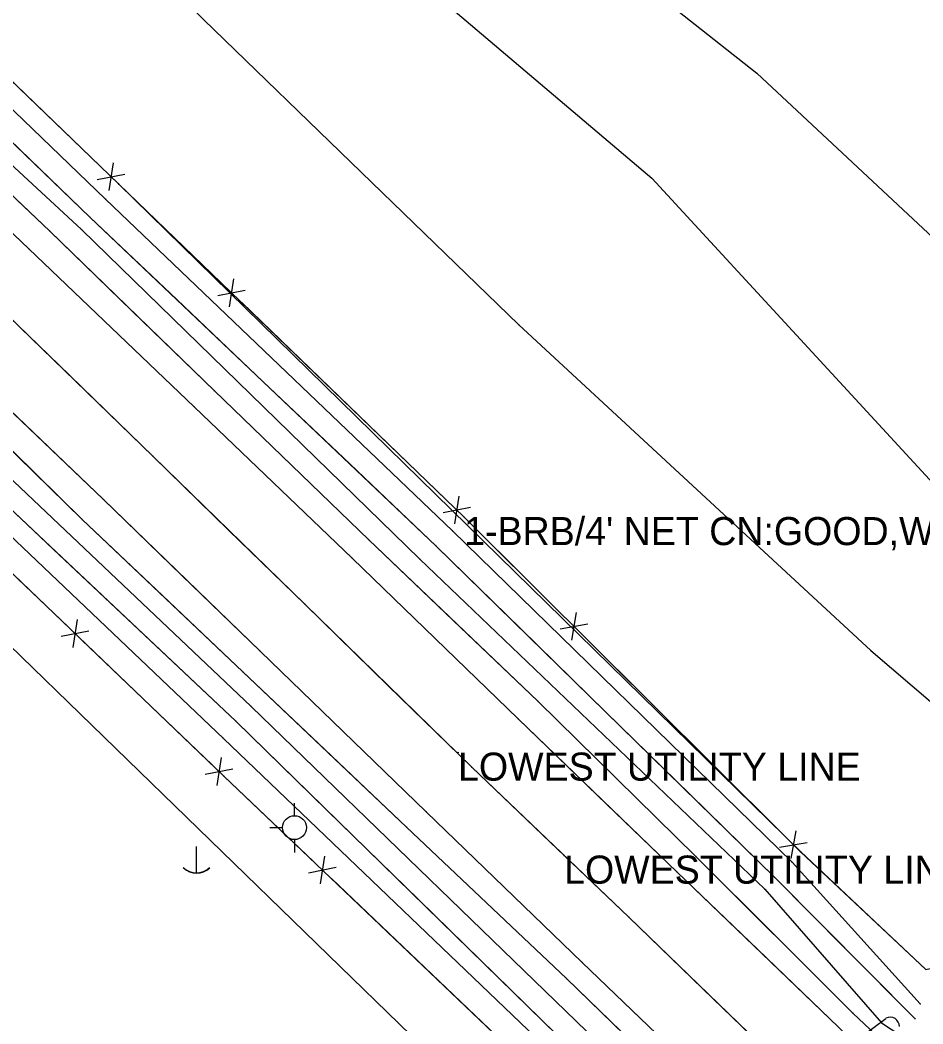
# Model space of a CAD drawing. Extents: x -99999 to 591807, y -99999 to 347168.
# Drawn here: x 588067.4 to 588228.1, y 346318.1 to 346496.8 of the extents above; entities that cross this region are included whole.
import ezdxf

# ---------------------------------------------------------------- set-up
doc = ezdxf.new("R2010")
doc.units = 0
for name, color, linetype in [('S_BREAKLINE', 7, 'Continuous'), ('S_DITCHLINE', 7, 'Continuous'), ('S_EDGE_PAVEMENT', 7, 'Continuous'), ('S_ELECTRIC_UTILITIES_ANNOT', 7, 'Continuous'), ('S_FENCE', 7, 'Continuous'), ('S_FENCE_ANNOT', 7, 'Continuous'), ('S_GRD_PT_SYM', 7, 'Continuous'), ('S_MAILBOX', 7, 'Continuous'), ('S_MSC_PT_SYM', 7, 'Continuous'), ('S_PAVEMENT_CROWN', 7, 'Continuous'), ('S_RDW_PT_SYM', 7, 'Continuous'), ('S_SHOULDER', 7, 'Continuous'), ('S_UTILITY_POLE', 7, 'Continuous'), ('S_UTL_PT_SYM', 7, 'Continuous'), ('S_WATER_UTILITIES', 7, 'Continuous')]:
    doc.layers.add(name, color=color, linetype=linetype)

msp = doc.modelspace()

# ---------------------------------------------------------------- linework, layer by layer
at = {"layer": 'S_BREAKLINE'}
for points in [[(588079.01, 346587.76), (588136.65, 346536.23), (588198.57, 346487.33), (588257.7, 346432.13), (588290.98, 346405.27)], [(588068.82, 346576.78), (588120.74, 346518.8), (588179.85, 346468.66), (588236.95, 346406.71), (588277.38, 346385.2)], [(588044.07, 346552.25), (588100.02, 346496.92), (588156.19, 346442.58), (588218.84, 346384.62), (588256.48, 346352.46)], [(588019.86, 346530.29), (588084.91, 346467.67), (588206.31, 346348.84), (588228.63, 346327.82), (588249.2, 346332.53)], [(588017.81, 346527.33), (588082.58, 346464.95), (588144.38, 346405.87), (588204.84, 346346.9), (588227.65, 346321.7)], [(588012.4, 346520.54), (588078.31, 346459.52), (588138.59, 346400.83), (588199.97, 346342.1), (588220.75, 346318.33), (588226.1, 346314.84), (588229.3, 346314.78), (588230.76, 346317.53)], [(587985.01, 346494.14), (588043.41, 346436.28), (588108.56, 346374.61), (588173.85, 346311.36), (588242.38, 346247.25), (588302.7, 346186.99), (588369.16, 346122.22), (588383.21, 346097.17), (588432.31, 346045.45), (588485.71, 345983.72), (588533.05, 345919.6)], [(587978.95, 346487.85), (588038.25, 346431.02), (588103.62, 346368.92), (588168.93, 346306.43), (588238, 346241.18), (588296.13, 346179.85), (588360.54, 346112.54), (588377.94, 346092.95), (588425.83, 346037.79), (588477.63, 345977.56), (588525.63, 345916.46)]]:
    msp.add_lwpolyline(points, dxfattribs=at)
at = {"layer": 'S_DITCHLINE'}
for points in [[(588015.07, 346524.14), (588079.87, 346461.68), (588141.49, 346403.19), (588201.74, 346344.19), (588226.74, 346319.06)], [(588015.07, 346524.14), (588031.27, 346508.52), (588047.47, 346492.91), (588063.67, 346477.29), (588079.87, 346461.68), (588095.28, 346447.05), (588110.68, 346432.43), (588126.09, 346417.81), (588141.49, 346403.19), (588156.55, 346388.44), (588171.62, 346373.69), (588186.68, 346358.94), (588201.74, 346344.19), (588214.24, 346331.62), (588226.74, 346319.06)], [(587981.38, 346490.49), (588040.72, 346433.29), (588105.81, 346371.99), (588170.92, 346308.42), (588239.53, 346243.97), (588298.87, 346183.24), (588365.05, 346118.27), (588381.6, 346095.52), (588429.37, 346040.98), (588482.84, 345982.86), (588529.72, 345920.18), (588553, 345879.12), (588569.51, 345828.65), (588585.87, 345761.88), (588598.5, 345693.11), (588612.58, 345591.71), (588620.74, 345530.5), (588634.95, 345464.48), (588639.41, 345427.12), (588638.6, 345425.11)], [(587981.38, 346490.49), (587996.22, 346476.19), (588011.05, 346461.89), (588025.89, 346447.59), (588040.72, 346433.29), (588056.99, 346417.97), (588073.27, 346402.64), (588089.54, 346387.32), (588105.81, 346371.99), (588122.09, 346356.1), (588138.36, 346340.21), (588154.64, 346324.31), (588170.92, 346308.42)]]:
    msp.add_lwpolyline(points, dxfattribs=at)
at = {"layer": 'S_EDGE_PAVEMENT'}
for points in [[(588006.51, 346515.67), (588037.25, 346486.28), (588068.97, 346456.07), (588098.41, 346427.99), (588126.49, 346401.05), (588156.06, 346372.42), (588184.38, 346345.17), (588213.09, 346317.55), (588241.74, 346289.83), (588275.21, 346257.52), (588304.28, 346229.62), (588334.12, 346200.8), (588363.95, 346171.7), (588391.18, 346144.84), (588419.55, 346117.13), (588447.95, 346088.7), (588472.86, 346062.77), (588495.2, 346037.93), (588515.96, 346012.84), (588538.3, 345983.93), (588553.85, 345961.48), (588569.44, 345935.94), (588581.55, 345913.63)], [(588006.51, 346515.67), (588021.88, 346500.97), (588037.25, 346486.28), (588053.11, 346471.18), (588068.97, 346456.07), (588083.69, 346442.03), (588098.41, 346427.99), (588112.45, 346414.52), (588126.49, 346401.05), (588141.27, 346386.73), (588156.06, 346372.42), (588170.22, 346358.8), (588184.38, 346345.17), (588198.74, 346331.36), (588213.09, 346317.55)], [(587990.04, 346499.66), (588021.44, 346469.83), (588052.98, 346439.41), (588082.26, 346411.47), (588110.16, 346384.47), (588139.71, 346355.89), (588167.47, 346329.09), (588196.94, 346300.74), (588228.68, 346270.07), (588258.37, 346241.41), (588287.79, 346213.57), (588317.3, 346184.82), (588347.78, 346154.95), (588374.65, 346128.54), (588403.23, 346100.42), (588430.53, 346073), (588454.75, 346047.65), (588476.4, 346023.75), (588497.81, 345997.87), (588518.5, 345970.8), (588533.24, 345949.77), (588549.25, 345924.48)], [(587990.04, 346499.66), (588005.74, 346484.74), (588021.44, 346469.83), (588037.21, 346454.62), (588052.98, 346439.41), (588067.62, 346425.44), (588082.26, 346411.47), (588096.21, 346397.97), (588110.16, 346384.47), (588124.94, 346370.18), (588139.71, 346355.89), (588153.59, 346342.49), (588167.47, 346329.09), (588182.21, 346314.92)]]:
    msp.add_lwpolyline(points, dxfattribs=at)
at = {"layer": 'S_FENCE'}
for p, q in [((588019.92, 346530.21), (588084.97, 346467.59)), ((588083.97, 346471.39), (588083.2, 346466.45)), ((588081.13, 346468.44), (588086.04, 346469.4)), ((588084.97, 346467.59), (588146.45, 346408.35)), ((588105.41, 346450.73), (588104.64, 346445.79)), ((588102.57, 346447.78), (588107.48, 346448.74)), ((588025.04, 346437.54), (588103.64, 346362.26)), ((588145.53, 346412.08), (588144.75, 346407.14)), ((588142.69, 346409.13), (588147.6, 346410.09)), ((588146.45, 346408.35), (588206.33, 346348.75)), ((588166.42, 346391.37), (588165.56, 346386.44)), ((588077.54, 346390.1), (588076.78, 346385.15)), ((588074.71, 346387.14), (588079.61, 346388.11)), ((588163.53, 346388.46), (588168.45, 346389.34)), ((588103.18, 346365.54), (588102.42, 346360.59)), ((588100.35, 346362.58), (588105.26, 346363.55)), ((588103.64, 346362.26), (588157.5, 346310.95)), ((588205.49, 346352.48), (588204.63, 346347.55)), ((588202.6, 346349.57), (588207.52, 346350.45)), ((588206.33, 346348.75), (588228.63, 346327.82)), ((588121.58, 346347.99), (588120.84, 346343.05)), ((588118.76, 346345.03), (588123.66, 346346.02))]:
    msp.add_line(p, q, dxfattribs=at)
for points in [[(588043.07, 346507.92), (588081.65, 346470.78)], [(588084.97, 346467.59), (588103.2, 346450.02)], [(588106.85, 346446.51), (588143.32, 346411.37)], [(588146.45, 346408.35), (588164.21, 346390.67)], [(588064.34, 346399.9), (588076, 346388.74)], [(588078.33, 346386.51), (588101.64, 346364.18)], [(588167.76, 346387.14), (588203.29, 346351.78)], [(588103.64, 346362.26), (588119.61, 346347.04)], [(588206.33, 346348.75), (588228.63, 346327.82)], [(588122.81, 346344), (588154.75, 346313.56)]]:
    msp.add_lwpolyline(points, dxfattribs=at)
at = {"layer": 'S_GRD_PT_SYM'}
for points in [[(588198.57, 346487.33), (588198.6, 346487.37), (588198.57, 346487.33), (588198.53, 346487.37), (588198.57, 346487.33), (588198.53, 346487.3), (588198.57, 346487.33), (588198.6, 346487.3)], [(588179.85, 346468.66), (588179.89, 346468.69), (588179.85, 346468.66), (588179.81, 346468.69), (588179.85, 346468.66), (588179.81, 346468.62), (588179.85, 346468.66), (588179.88, 346468.62)], [(588084.91, 346467.67), (588084.95, 346467.71), (588084.91, 346467.67), (588084.88, 346467.71), (588084.91, 346467.67), (588084.88, 346467.64), (588084.91, 346467.67), (588084.95, 346467.64)], [(588082.58, 346464.95), (588082.62, 346464.99), (588082.58, 346464.95), (588082.54, 346464.99), (588082.58, 346464.95), (588082.55, 346464.91), (588082.58, 346464.95), (588082.62, 346464.92)], [(588079.87, 346461.68), (588079.91, 346461.71), (588079.87, 346461.68), (588079.83, 346461.71), (588079.87, 346461.68), (588079.84, 346461.64), (588079.87, 346461.68), (588079.91, 346461.64)], [(588078.31, 346459.52), (588078.34, 346459.56), (588078.31, 346459.52), (588078.27, 346459.56), (588078.31, 346459.52), (588078.27, 346459.49), (588078.31, 346459.52), (588078.34, 346459.49)], [(588156.19, 346442.58), (588156.22, 346442.61), (588156.19, 346442.58), (588156.15, 346442.61), (588156.19, 346442.58), (588156.15, 346442.54), (588156.19, 346442.58), (588156.22, 346442.54)], [(588144.38, 346405.87), (588144.41, 346405.91), (588144.38, 346405.87), (588144.34, 346405.91), (588144.38, 346405.87), (588144.34, 346405.84), (588144.38, 346405.87), (588144.41, 346405.84)], [(588141.49, 346403.19), (588141.53, 346403.22), (588141.49, 346403.19), (588141.46, 346403.22), (588141.49, 346403.19), (588141.46, 346403.15), (588141.49, 346403.19), (588141.53, 346403.15)], [(588138.59, 346400.83), (588138.62, 346400.86), (588138.59, 346400.83), (588138.55, 346400.86), (588138.59, 346400.83), (588138.55, 346400.79), (588138.59, 346400.83), (588138.63, 346400.79)], [(588218.84, 346384.62), (588218.88, 346384.65), (588218.84, 346384.62), (588218.81, 346384.65), (588218.84, 346384.62), (588218.81, 346384.58), (588218.84, 346384.62), (588218.88, 346384.58)], [(588108.56, 346374.61), (588108.59, 346374.64), (588108.56, 346374.61), (588108.52, 346374.64), (588108.56, 346374.61), (588108.52, 346374.57), (588108.56, 346374.61), (588108.59, 346374.57)], [(588105.81, 346371.99), (588105.84, 346372.03), (588105.81, 346371.99), (588105.77, 346372.03), (588105.81, 346371.99), (588105.77, 346371.96), (588105.81, 346371.99), (588105.85, 346371.96)], [(588103.62, 346368.92), (588103.65, 346368.96), (588103.62, 346368.92), (588103.58, 346368.96), (588103.62, 346368.92), (588103.58, 346368.89), (588103.62, 346368.92), (588103.65, 346368.89)], [(588145.36, 346366.43), (588145.36, 346366.48), (588145.36, 346366.43), (588145.31, 346366.43), (588145.36, 346366.43), (588145.36, 346366.38), (588145.36, 346366.43), (588145.41, 346366.43)], [(588206.31, 346348.84), (588206.35, 346348.88), (588206.31, 346348.84), (588206.28, 346348.88), (588206.31, 346348.84), (588206.28, 346348.81), (588206.31, 346348.84), (588206.35, 346348.81)], [(588164.25, 346348.1), (588164.25, 346348.15), (588164.25, 346348.1), (588164.2, 346348.1), (588164.25, 346348.1), (588164.25, 346348.05), (588164.25, 346348.1), (588164.3, 346348.1)], [(588204.84, 346346.9), (588204.88, 346346.94), (588204.84, 346346.9), (588204.81, 346346.94), (588204.84, 346346.9), (588204.8, 346346.87), (588204.84, 346346.9), (588204.87, 346346.87)], [(588201.74, 346344.19), (588201.77, 346344.22), (588201.74, 346344.19), (588201.7, 346344.22), (588201.74, 346344.19), (588201.7, 346344.15), (588201.74, 346344.19), (588201.77, 346344.15)], [(588199.97, 346342.1), (588200.01, 346342.13), (588199.97, 346342.1), (588199.94, 346342.13), (588199.97, 346342.1), (588199.93, 346342.06), (588199.97, 346342.1), (588200, 346342.06)], [(588227.65, 346321.7), (588227.69, 346321.74), (588227.65, 346321.7), (588227.62, 346321.74), (588227.65, 346321.7), (588227.62, 346321.67), (588227.65, 346321.7), (588227.69, 346321.66)], [(588220.75, 346318.33), (588220.78, 346318.37), (588220.75, 346318.33), (588220.71, 346318.36), (588220.75, 346318.33), (588220.72, 346318.29), (588220.75, 346318.33), (588220.79, 346318.3)], [(588226.74, 346319.06), (588226.77, 346319.1), (588226.74, 346319.06), (588226.7, 346319.1), (588226.74, 346319.06), (588226.7, 346319.03), (588226.74, 346319.06), (588226.77, 346319.03)]]:
    msp.add_lwpolyline(points, close=True, dxfattribs=at)
at = {"layer": 'S_MAILBOX'}
msp.add_line((588217.4, 346316.02), (588221.53, 346319.13), dxfattribs=at)
msp.add_arc((588222.3, 346317.66), 1.66, 0, 117.5718, dxfattribs=at)
at = {"layer": 'S_MSC_PT_SYM'}
for points in [[(588084.97, 346467.59), (588084.97, 346467.64), (588084.97, 346467.59), (588084.92, 346467.59), (588084.97, 346467.59), (588084.97, 346467.54), (588084.97, 346467.59), (588085.02, 346467.59)], [(588146.45, 346408.35), (588146.45, 346408.4), (588146.45, 346408.35), (588146.4, 346408.35), (588146.45, 346408.35), (588146.45, 346408.3), (588146.45, 346408.35), (588146.5, 346408.35)], [(588146.45, 346408.35), (588146.45, 346408.4), (588146.45, 346408.35), (588146.4, 346408.35), (588146.45, 346408.35), (588146.45, 346408.3), (588146.45, 346408.35), (588146.5, 346408.35)], [(588103.64, 346362.26), (588103.64, 346362.31), (588103.64, 346362.26), (588103.59, 346362.26), (588103.64, 346362.26), (588103.64, 346362.21), (588103.64, 346362.26), (588103.69, 346362.26)], [(588206.33, 346348.75), (588206.33, 346348.8), (588206.33, 346348.75), (588206.28, 346348.75), (588206.33, 346348.75), (588206.33, 346348.7), (588206.33, 346348.75), (588206.38, 346348.75)]]:
    msp.add_lwpolyline(points, dxfattribs=at)
at = {"layer": 'S_PAVEMENT_CROWN'}
for points in [[(587997.94, 346508.04), (588029.71, 346477.77), (588061.36, 346447.92), (588091.09, 346419.11), (588118.07, 346392.84), (588147.79, 346363.81), (588175.77, 346337.12), (588205.85, 346308.09), (588236.22, 346278.66), (588266.55, 346249.5), (588296.48, 346221.11), (588325.95, 346192.27), (588355.72, 346163.52), (588383.28, 346136.41), (588411.18, 346108.72), (588439.24, 346080.6), (588464.53, 346055.01), (588485.92, 346030.52), (588506.56, 346005.75), (588528.34, 345977.31), (588543.88, 345955.52), (588560.06, 345929.96), (588571.31, 345908.67)], [(587997.94, 346508.04), (588013.83, 346492.91), (588029.71, 346477.77), (588045.53, 346462.85), (588061.36, 346447.92), (588076.23, 346433.52), (588091.09, 346419.11), (588104.58, 346405.98), (588118.07, 346392.84), (588132.93, 346378.33), (588147.79, 346363.81), (588161.78, 346350.46), (588175.77, 346337.12), (588190.81, 346322.6), (588205.85, 346308.09)]]:
    msp.add_lwpolyline(points, dxfattribs=at)
at = {"layer": 'S_RDW_PT_SYM'}
for points in [[(588072.71, 346459.21), (588072.75, 346459.25), (588072.71, 346459.21), (588072.67, 346459.24), (588072.71, 346459.21), (588072.68, 346459.17), (588072.71, 346459.21), (588072.75, 346459.18)], [(588068.97, 346456.07), (588069, 346456.11), (588068.97, 346456.07), (588068.93, 346456.11), (588068.97, 346456.07), (588068.93, 346456.04), (588068.97, 346456.07), (588069, 346456.04)], [(588102.02, 346430.81), (588102.05, 346430.84), (588102.02, 346430.81), (588101.98, 346430.84), (588102.02, 346430.81), (588101.98, 346430.77), (588102.02, 346430.81), (588102.06, 346430.77)], [(588098.41, 346427.99), (588098.45, 346428.03), (588098.41, 346427.99), (588098.38, 346428.02), (588098.41, 346427.99), (588098.38, 346427.95), (588098.41, 346427.99), (588098.45, 346427.96)], [(588091.09, 346419.11), (588091.13, 346419.15), (588091.09, 346419.11), (588091.06, 346419.15), (588091.09, 346419.11), (588091.06, 346419.08), (588091.09, 346419.11), (588091.13, 346419.08)], [(588082.26, 346411.47), (588082.29, 346411.51), (588082.26, 346411.47), (588082.22, 346411.51), (588082.26, 346411.47), (588082.23, 346411.44), (588082.26, 346411.47), (588082.3, 346411.44)], [(588078.44, 346407.93), (588078.48, 346407.96), (588078.44, 346407.93), (588078.41, 346407.96), (588078.44, 346407.93), (588078.41, 346407.89), (588078.44, 346407.93), (588078.48, 346407.89)], [(588129.46, 346404.3), (588129.49, 346404.34), (588129.46, 346404.3), (588129.42, 346404.34), (588129.46, 346404.3), (588129.42, 346404.27), (588129.46, 346404.3), (588129.5, 346404.27)], [(588126.49, 346401.05), (588126.52, 346401.08), (588126.49, 346401.05), (588126.45, 346401.08), (588126.49, 346401.05), (588126.45, 346401.01), (588126.49, 346401.05), (588126.52, 346401.01)], [(588118.07, 346392.84), (588118.11, 346392.88), (588118.07, 346392.84), (588118.04, 346392.88), (588118.07, 346392.84), (588118.04, 346392.81), (588118.07, 346392.84), (588118.11, 346392.81)], [(588110.16, 346384.47), (588110.19, 346384.51), (588110.16, 346384.47), (588110.12, 346384.51), (588110.16, 346384.47), (588110.12, 346384.44), (588110.16, 346384.47), (588110.19, 346384.44)], [(588107.07, 346380.79), (588107.11, 346380.83), (588107.07, 346380.79), (588107.04, 346380.83), (588107.07, 346380.79), (588107.04, 346380.76), (588107.07, 346380.79), (588107.11, 346380.76)], [(588159.58, 346375.55), (588159.61, 346375.59), (588159.58, 346375.55), (588159.54, 346375.59), (588159.58, 346375.55), (588159.54, 346375.52), (588159.58, 346375.55), (588159.61, 346375.52)], [(588156.06, 346372.42), (588156.1, 346372.46), (588156.06, 346372.42), (588156.03, 346372.45), (588156.06, 346372.42), (588156.03, 346372.38), (588156.06, 346372.42), (588156.1, 346372.38)], [(588147.79, 346363.81), (588147.83, 346363.85), (588147.79, 346363.81), (588147.76, 346363.85), (588147.79, 346363.81), (588147.76, 346363.78), (588147.79, 346363.81), (588147.83, 346363.78)], [(588139.71, 346355.89), (588139.75, 346355.93), (588139.71, 346355.89), (588139.68, 346355.93), (588139.71, 346355.89), (588139.68, 346355.86), (588139.71, 346355.89), (588139.75, 346355.86)], [(588136.2, 346353.17), (588136.24, 346353.21), (588136.2, 346353.17), (588136.17, 346353.21), (588136.2, 346353.17), (588136.17, 346353.14), (588136.2, 346353.17), (588136.24, 346353.14)], [(588187.72, 346347.96), (588187.75, 346348), (588187.72, 346347.96), (588187.68, 346348), (588187.72, 346347.96), (588187.68, 346347.93), (588187.72, 346347.96), (588187.75, 346347.93)], [(588184.38, 346345.17), (588184.41, 346345.21), (588184.38, 346345.17), (588184.34, 346345.21), (588184.38, 346345.17), (588184.34, 346345.14), (588184.38, 346345.17), (588184.42, 346345.14)], [(588175.77, 346337.12), (588175.81, 346337.15), (588175.77, 346337.12), (588175.74, 346337.15), (588175.77, 346337.12), (588175.74, 346337.08), (588175.77, 346337.12), (588175.81, 346337.08)], [(588167.47, 346329.09), (588167.51, 346329.13), (588167.47, 346329.09), (588167.44, 346329.13), (588167.47, 346329.09), (588167.44, 346329.06), (588167.47, 346329.09), (588167.51, 346329.06)], [(588164.68, 346326.19), (588164.71, 346326.23), (588164.68, 346326.19), (588164.64, 346326.23), (588164.68, 346326.19), (588164.64, 346326.16), (588164.68, 346326.19), (588164.71, 346326.16)], [(588215.66, 346320.05), (588215.7, 346320.09), (588215.66, 346320.05), (588215.63, 346320.08), (588215.66, 346320.05), (588215.63, 346320.01), (588215.66, 346320.05), (588215.7, 346320.02)]]:
    msp.add_lwpolyline(points, close=True, dxfattribs=at)
at = {"layer": 'S_SHOULDER'}
for points in [[(588010.2, 346518.27), (588040.87, 346489.37), (588072.71, 346459.21), (588102.02, 346430.81), (588129.46, 346404.3), (588159.58, 346375.55), (588187.72, 346347.96), (588215.66, 346320.05), (588223.88, 346312.27)], [(588010.2, 346518.27), (588025.53, 346503.82), (588040.87, 346489.37), (588056.79, 346474.29), (588072.71, 346459.21), (588087.36, 346445.01), (588102.02, 346430.81), (588115.74, 346417.56), (588129.46, 346404.3), (588144.52, 346389.93), (588159.58, 346375.55), (588173.65, 346361.76), (588187.72, 346347.96), (588201.69, 346334.01), (588215.66, 346320.05), (588223.88, 346312.27)], [(587987.1, 346496.67), (588018.38, 346466.6), (588049.78, 346436.07), (588078.44, 346407.93), (588107.07, 346380.79), (588136.2, 346353.17), (588164.68, 346326.19), (588193.77, 346298.03), (588226.04, 346266.74), (588255.76, 346238.66), (588285.11, 346210.85), (588314.36, 346182.4), (588345, 346152.62), (588372.24, 346126.49), (588400.28, 346098.36), (588427.77, 346070.6), (588452.08, 346045.58), (588473.81, 346021.51), (588494.82, 345995.69), (588515.11, 345968.81), (588530.37, 345947.67), (588545.69, 345922.75)], [(587987.1, 346496.67), (588002.74, 346481.64), (588018.38, 346466.6), (588034.08, 346451.34), (588049.78, 346436.07), (588064.11, 346422), (588078.44, 346407.93), (588092.76, 346394.36), (588107.07, 346380.79), (588121.64, 346366.98), (588136.2, 346353.17), (588150.44, 346339.68), (588164.68, 346326.19), (588179.22, 346312.11)]]:
    msp.add_lwpolyline(points, dxfattribs=at)
at = {"layer": 'S_UTILITY_POLE'}
for p, q in [((588116.24, 346355.18), (588116.24, 346357.43)), ((588114.15, 346353.05), (588111.83, 346353.05)), ((588116.32, 346348.63), (588116.32, 346350.96)), ((588098.73, 346349.72), (588098.73, 346344.99)), ((588098.76, 346349.69), (588098.76, 346344.96))]:
    msp.add_line(p, q, dxfattribs=at)
msp.add_circle((588116.25, 346353.07), 2.13, dxfattribs=at)
for centre in [(588098.79, 346348.42), (588098.82, 346348.39)]:
    msp.add_arc(centre, 3.41, 226.3972, 313.6028, dxfattribs=at)
at = {"layer": 'S_UTL_PT_SYM'}
for points in [[(588145.36, 346366.43), (588145.36, 346366.48), (588145.36, 346366.43), (588145.31, 346366.43), (588145.36, 346366.43), (588145.36, 346366.38), (588145.36, 346366.43), (588145.41, 346366.43)], [(588164.25, 346348.1), (588164.25, 346348.15), (588164.25, 346348.1), (588164.2, 346348.1), (588164.25, 346348.1), (588164.25, 346348.05), (588164.25, 346348.1), (588164.3, 346348.1)]]:
    msp.add_lwpolyline(points, dxfattribs=at)
at = {"layer": 'S_WATER_UTILITIES'}
msp.add_line((588039.85, 346410.45), (588158.22, 346295.54), dxfattribs=at)

# ---------------------------------------------------------------- texts
at = {"layer": 'S_ELECTRIC_UTILITIES_ANNOT'}
for p in [(588145.36, 346361.43), (588164.25, 346343.1)]:
    msp.add_text('LOWEST UTILITY LINE', height=5, dxfattribs=at).set_placement(p)
at = {"layer": 'S_FENCE_ANNOT'}
msp.add_text("1-BRB/4' NET CN:GOOD,WOOD/STEEL", height=5, dxfattribs=at).set_placement((588146.45, 346403.35))

doc.saveas('drawing.dxf')
